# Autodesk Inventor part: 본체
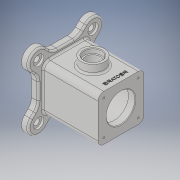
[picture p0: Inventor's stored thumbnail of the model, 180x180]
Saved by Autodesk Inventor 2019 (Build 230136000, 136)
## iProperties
Created: 2021-01
Part Number: 본체
Material: 일반
Document SubType Name: Modeling
Designer: 3dpro9
Density: 1 g/cm^3
Appearance: 기본값
Mass: 385.865 g
Surface Area: 854.371 cm^2
Volume: 385.865 cm^3
Author: 3dpro9
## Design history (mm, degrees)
sketch "스케치1"
  geometry: L1 (48, 48)-(-48, -48); L2 (-48, 48)-(48, -48); L3 (48, -22.544)-(48, 22.544); L4 (34.648, 60.104)-(22.544, 48); L5 (60.104, 34.648)-(48, 22.544); L6 (60.104, -34.648)-(48, -22.544); L7 (34.648, -60.104)-(22.544, -48); L8 (-48, -22.544)-(-60.104, -34.648); L9 (-22.544, -48)-(-34.648, -60.104); L10 (-22.544, 48)-(-34.648, 60.104); L11 (-48, 22.544)-(-60.104, 34.648); L12 (-22.544, -48)-(22.544, -48); L13 (-48, 22.544)-(-48, -22.544); L14 (22.544, 48)-(-22.544, 48); L15 (0, -101.965)-(0, 101.965) reference; L16 (-101.965, 0)-(101.965, 0) reference; A1 r 18 centre (47.376, 47.376) between (60.104, 34.648) and (34.648, 60.104); A2 r 18 centre (47.376, -47.376) between (34.648, -60.104) and (60.104, -34.648); A3 r 18 centre (-47.376, 47.376) between (-34.648, 60.104) and (-60.104, 34.648); A4 r 18 centre (-47.376, -47.376) between (-60.104, -34.648) and (-34.648, -60.104); A5 r 67 centre (0, 0) between (47.376, -47.376) and (47.376, 47.376); 1 further point
  constraints: 28 end point, 12 point on circle, 8 tangent, 6 parallel, 5 centre point, 4 point on line, 3 equal radius, 2 midpoint, 1 coincident, 1 horizontal, 1 perpendicular, 2 other
  dimensions: "d0" = 96 distance of L2.start L1.end; "d1" = 96 distance of L1.end L2.end; "d2" = 134 diameter of A5; "d3" = 36 diameter of A2; "d4" = 45 deg angle of L16 L2; "d5" = 45 deg angle of L1 L16; "d6" = 96 distance between parallel lines of L12 L14; "d7" = 96 distance between parallel lines of L3 L13; "d8" = 135 deg angle of L3 L5; "d9" = 135 deg angle of L6 L3; "d10" = 135 deg angle of L12 L9; "d11" = 135 deg angle of L14 L10
extrude "돌출1" new body sketch "스케치1" distance "d12" = 12; taper "d13" = 0 deg
sketch "스케치2"
  geometry: L1 (-40, 40)-(40, 40); L2 (40, 40)-(40, -40); L3 (40, -40)-(-40, -40); L4 (-40, -40)-(-40, 40); L5 (-40, 40)-(40, -40); L6 (40, 40)-(-40, -40); 1 further point
  constraints: 12 end point, 2 midpoint, 2 parallel, 1 horizontal, 1 perpendicular
  dimensions: "d14" = 80 distance of L2.end L3.end; "d15" = 80 distance of L1.end L2.end
extrude "돌출2" join sketch "스케치2" distance "d16" = 96; taper "d17" = 0 deg
sketch "스케치3"
  geometry: L1 (122.903, 0)-(-21.468, 0); L2 (108, 25)-(96, 25); L3 (96, 25)-(96, 35); L4 (96, 35)-(12, 35); L5 (12, 35)-(12, 25); L6 (12, 25)-(0, 25); L7 (108, 40)-(108, -40) reference; L8 (0, -22.544)-(0, 22.544) reference; L9 (0, 25)-(0, 0); L10 (108, 25)-(108, 0); 1 further point
  constraints: 16 end point, 5 point on line, 4 perpendicular, 2 horizontal, 1 collinear, 1 midpoint, 1 vertical alignment
  dimensions: "d18" = 50 diameter of L2 L1; "d19" = 70 diameter of L4 L1; "d20" = 12 distance of L5.end L6.end; "d21" = 12 distance of L2.start L2.end
revolve "회전1" sketch "스케치3" stored, may be unused: angle "d22" = 90 deg
sketch "스케치4"
  geometry: L1 (-12, 17.456)-(-12, 62.544) reference; C1 r 20 at (47, 40); 2 further points
  constraints: 1 centre point, 1 horizontal alignment, 1 midpoint
  dimensions: "d23" = 40 diameter of C1; "d24" = 59 distance from line of L1 C1.centre
extrude "돌출3" join sketch "스케치4" distance "d25" = 15; taper "d26" = 0 deg
sketch "스케치5"
  geometry: C1 r 20 at (0, 0) reference; 2 further points
  constraints: 1 coincident
sketch "스케치7"
  geometry: L1 (91.527, 0)-(-91.527, 0) reference; L2 (0, -91.527)-(0, 91.527) reference; L3 (30, 30)-(0, 0); L4 (-30, 30)-(0, 0); L5 (0, 0)-(-30, -30); L6 (0, 0)-(30, -30); C1 r 25 at (0, 0) reference; 1 further point
  constraints: 8 end point, 2 horizontal alignment, 2 vertical alignment, 1 midpoint
  dimensions: "d34" = 45 deg angle of L2 L3; "d35" = 45 deg angle of L2 L4; "d36" = 45 deg angle of L2 L5; "d37" = 45 deg angle of L6 L2; "d38" = 60 distance of L6.end L5.end
hole "구멍2" sketch "스케치7" at (30, 30), (30, -30), (-30, -30), (-30, 30) diameter "d39" = 3.242; stored, may be unused: countersink angle "d43" = 90 deg, drill point angle "d45" = 118 deg; dims "d40" = 8, "d41" = 30, "d42" = 8, "d44" = 10
node "작업 평면1"
sketch "스케치8"
  geometry: A1 r 18 centre (-47.376, 47.376) between (-34.648, 60.104) and (-60.104, 34.648) reference; 2 further points
  constraints: 1 coincident
hole "구멍3" sketch "스케치8" at (-47.376, 47.376) diameter "d47" = 10; stored, may be unused: countersink angle "d51" = 90 deg, drill point angle "d53" = 118 deg; dims "d48" = 8, "d49" = 18, "d50" = 4, "d52" = 10
hole "구멍4" sketch "스케치5" diameter "d54" = 25; stored, may be unused: countersink angle "d58" = 90 deg, drill point angle "d60" = 0 deg; dims "d55" = 8, "d56" = 30, "d57" = 8, "d59" = 10
sketch "스케치9"
  geometry: L1 (96, 80)-(96, 0) reference; L2 (-33.6, 40)-(117.6, 40) reference; 2 further points
  constraints: 1 point on line, 1 other
  dimensions: "d61" = 10 distance from line of point (86, 40) L1
feature "엠보싱1" sketch "스케치9" dims "d0" = 96, "d1" = 96, "d2" = 134, "d3" = 36, "d4" = 45 deg, "d5" = 45 deg, "d6" = 96, "d7" = 96, "d8" = 135 deg, "d9" = 135 deg, "d10" = 135 deg, "d11" = 135 deg, "d62" = 0.5, "d63" = 0
fillet "모깎기1" dims "d64" = 10
fillet "모깎기2" dims "d65" = 20
fillet "모깎기3" dims "d66" = 3
chamfer "모따기1" distance "d67" = 1; stored, may be unused: second distance "d68" = 2, angle "d69" = 45 deg
chamfer "모따기2" distance "d70" = 1; stored, may be unused: second distance "d71" = 2, angle "d72" = 45 deg
chamfer "모따기3" distance "d73" = 1; stored, may be unused: second distance "d74" = 2, angle "d75" = 45 deg
fillet "모깎기4" dims "d76" = 3
fillet "모깎기5" dims "d77" = 3
fillet "모깎기6" dims "d78" = 3
node "솔리드1"
mirror "미러1"
mirror "미러2"
mirror "미러3"
other parameters: "d46" = -54
